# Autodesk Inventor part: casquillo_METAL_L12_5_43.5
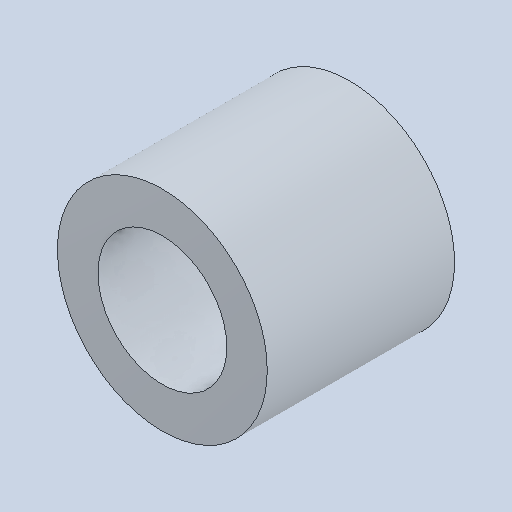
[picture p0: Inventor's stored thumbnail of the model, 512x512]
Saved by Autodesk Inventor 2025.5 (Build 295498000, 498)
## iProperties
Created: 2026-10
Part Number: casquillo_METAL_L12_5_43.5
Material: Genérico
Document SubType Name: Modeling
Designer: Luis M
Density: 1 g/cm^3
Appearance: Valor por defecto
Author: Luis M
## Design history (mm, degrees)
feature "Base1"
node "Sólido1"
